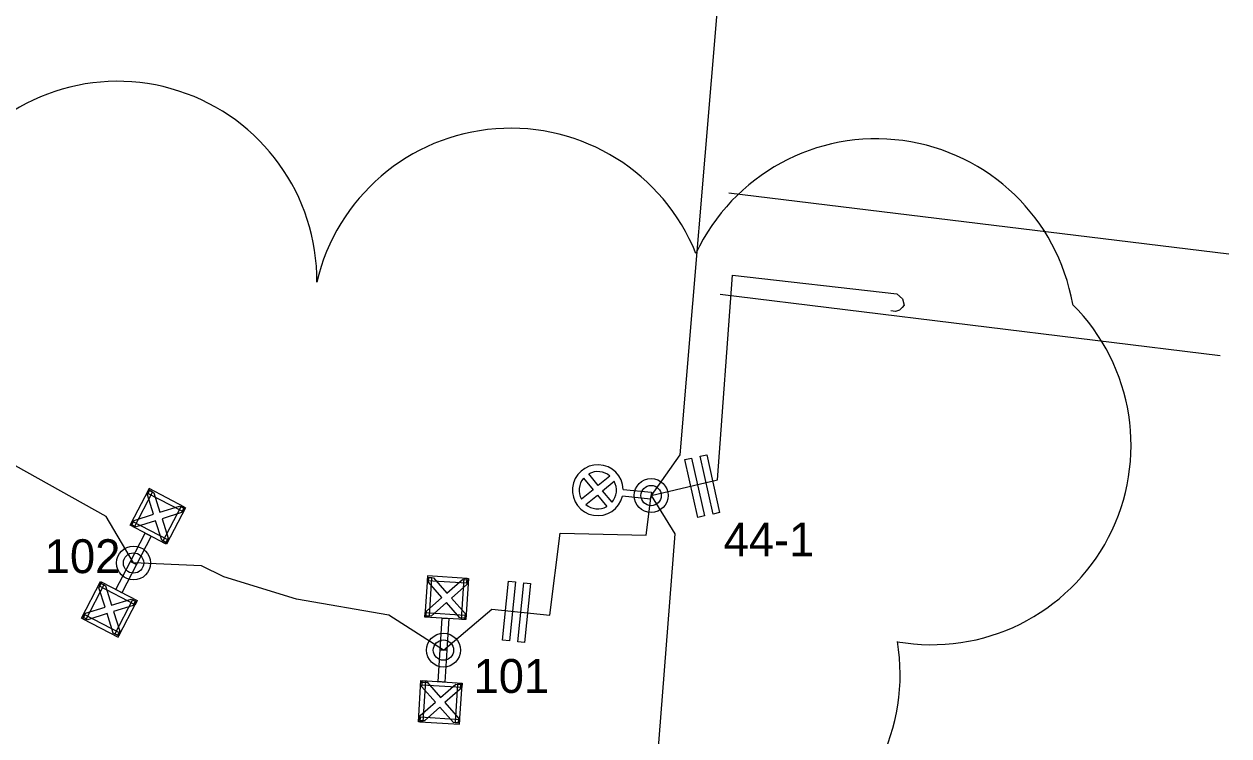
# Model space of a CAD drawing. Extents: x 25497851 to 25498523, y 6686544 to 6687372.
# Drawn here: x 25498190.6 to 25498297.2, y 6686990.4 to 6687053.4 of the extents above; entities that cross this region are included whole.
import ezdxf

# ---------------------------------------------------------------- set-up
doc = ezdxf.new("R2010")
doc.units = 0
for name, color, linetype in [('KAAPELI', 7, 'Continuous'), ('KEYGWT_ANNOTATION', 7, 'Continuous'), ('MUU_SUUNNITELMAVIIVA', 7, 'Continuous'), ('MUU_UV-SUUNNITELMASYMBOLI', 7, 'Continuous'), ('PYLVAS', 7, 'Continuous'), ('TEKSTI_SUUNNITELMA-ALUE', 7, 'Continuous'), ('TieAlue_ajorata', 7, 'Continuous'), ('VALAISIN', 7, 'Continuous')]:
    doc.layers.add(name, color=color, linetype=linetype)

msp = doc.modelspace()

# ---------------------------------------------------------------- linework, layer by layer
at = {"layer": 'KAAPELI'}
for points in [[(25498250.22, 6687059.49), (25498251.96, 6687055.15), (25498248.64, 6687015.33), (25498246.09, 6687011.72)], [(25498246.09, 6687011.72), (25498251.96, 6687013.1), (25498253.29, 6687031.23), (25498267.85, 6687029.58), (25498268.35, 6687029.13), (25498268.49, 6687028.57), (25498268.31, 6687028.35), (25498268.09, 6687028.13), (25498267.72, 6687028.01), (25498267.31, 6687028.08)], [(25498200.27, 6687005.75), (25498197.85, 6687009.86), (25498181.51, 6687018.98), (25498176.94, 6687018.9)], [(25498227.71, 6686998.04), (25498232, 6687001.66), (25498237.11, 6687001.14), (25498238.03, 6687008.39), (25498245.66, 6687008.21), (25498246.09, 6687011.72)], [(25498246.09, 6687011.72), (25498248.18, 6687008.34), (25498245.03, 6686967.87), (25498241.98, 6686963.86)], [(25498227.71, 6686998.04), (25498222.86, 6687001.14), (25498214.69, 6687002.55), (25498208.26, 6687004.51), (25498206.28, 6687005.51), (25498200.27, 6687005.75)]]:
    msp.add_lwpolyline(points, dxfattribs=at)
at = {"layer": 'MUU_SUUNNITELMAVIIVA'}
for centre, radius, start, end in [((25498198.85, 6687030.73), 17.65, 359.5582, 144.5582), ((25498233.67, 6687026.58), 17.65, 21.8381, 166.8381), ((25498266.02, 6687025.64), 17.65, 9.8286, 154.8286), ((25498270.94, 6687016.16), 17.64, 260.0364, 45.0364), ((25498250.49, 6686995.87), 17.65, 224.5286, 9.5286)]:
    msp.add_arc(centre, radius, start, end, dxfattribs=at)
at = {"layer": 'MUU_UV-SUUNNITELMASYMBOLI'}
for p, q in [((25498250.42, 6687015.2), (25498251.01, 6687015.33)), ((25498251.57, 6687010.07), (25498250.42, 6687015.2)), ((25498251.01, 6687015.33), (25498252.15, 6687010.21)), ((25498249.09, 6687014.9), (25498249.68, 6687015.03)), ((25498250.24, 6687009.78), (25498249.09, 6687014.9)), ((25498249.68, 6687015.03), (25498250.82, 6687009.91)), ((25498250.82, 6687009.91), (25498250.24, 6687009.78)), ((25498252.15, 6687010.21), (25498251.57, 6687010.07)), ((25498232.94, 6686998.91), (25498233.47, 6687004.13)), ((25498233.47, 6687004.13), (25498234.07, 6687004.07)), ((25498234.07, 6687004.07), (25498233.54, 6686998.85)), ((25498234.3, 6686998.77), (25498234.82, 6687003.99)), ((25498234.82, 6687003.99), (25498235.42, 6687003.93)), ((25498235.42, 6687003.93), (25498234.89, 6686998.71)), ((25498233.54, 6686998.85), (25498232.94, 6686998.91)), ((25498234.89, 6686998.71), (25498234.3, 6686998.77))]:
    msp.add_line(p, q, dxfattribs=at)
at = {"layer": 'PYLVAS'}
for centre, radius in [((25498246.09, 6687011.72), 1.5), ((25498246.09, 6687011.72), 0.9), ((25498200.27, 6687005.75), 1.5), ((25498200.27, 6687005.75), 1.5), ((25498200.27, 6687005.75), 0.9), ((25498200.27, 6687005.75), 0.9), ((25498227.71, 6686998.04), 1.5), ((25498227.71, 6686998.04), 0.9)]:
    msp.add_circle(centre, radius, dxfattribs=at)
at = {"layer": 'TieAlue_ajorata'}
for p, q in [((25498252.97, 6687038.5), (25498297.24, 6687033.1)), ((25498252.2, 6687029.53), (25498296.47, 6687024.12))]:
    msp.add_line(p, q, dxfattribs=at)
at = {"layer": 'VALAISIN'}
for p, q in [((25498240.11, 6687013.25), (25498240.95, 6687012.23)), ((25498241.41, 6687012.61), (25498240.57, 6687013.63)), ((25498242.44, 6687013.44), (25498241.41, 6687012.61)), ((25498241.79, 6687012.14), (25498242.81, 6687012.98)), ((25498240.95, 6687012.23), (25498239.92, 6687011.39)), ((25498242.63, 6687011.12), (25498241.79, 6687012.14)), ((25498243.62, 6687012.26), (25498246.11, 6687012.01)), ((25498246.11, 6687012.01), (25498246.05, 6687011.41)), ((25498240.3, 6687010.93), (25498241.33, 6687011.76)), ((25498241.33, 6687011.76), (25498242.16, 6687010.74)), ((25498246.05, 6687011.41), (25498243.56, 6687011.66))]:
    msp.add_line(p, q, dxfattribs=at)
for points in [[(25498201.58, 6687012.22), (25498200.01, 6687009.2), (25498200.37, 6687009.02), (25498201.94, 6687012.03)], [(25498202.77, 6687007.77), (25498202.22, 6687009.49), (25498200.5, 6687008.95), (25498200.12, 6687009.14), (25498200.32, 6687009.52), (25498202.04, 6687010.06), (25498201.5, 6687011.78), (25498201.69, 6687012.16), (25498202.07, 6687011.96), (25498202.61, 6687010.24), (25498204.34, 6687010.78), (25498204.71, 6687010.59), (25498204.52, 6687010.21), (25498202.79, 6687009.67), (25498203.34, 6687007.95), (25498203.14, 6687007.57)], [(25498204.59, 6687010.34), (25498204.77, 6687010.69), (25498201.64, 6687012.33), (25498201.46, 6687011.97)], [(25498202.84, 6687007.59), (25498204.52, 6687010.82), (25498204.88, 6687010.64), (25498203.19, 6687007.41)], [(25498199.96, 6687009.09), (25498200.14, 6687009.45), (25498203.27, 6687007.82), (25498203.09, 6687007.46)], [(25498200.01, 6687005.89), (25498201.31, 6687008.39), (25498201.84, 6687008.11), (25498200.54, 6687005.61)], [(25498200.54, 6687005.61), (25498199.24, 6687003.12), (25498198.71, 6687003.4), (25498200.01, 6687005.89)], [(25498226.28, 6687004.48), (25498226.07, 6687001.08), (25498226.47, 6687001.06), (25498226.68, 6687004.45)], [(25498229.17, 6687000.89), (25498227.97, 6687002.25), (25498226.61, 6687001.05), (25498226.19, 6687001.08), (25498226.22, 6687001.5), (25498227.57, 6687002.7), (25498226.37, 6687004.05), (25498226.4, 6687004.47), (25498226.82, 6687004.45), (25498228.02, 6687003.09), (25498229.38, 6687004.29), (25498229.8, 6687004.26), (25498229.77, 6687003.84), (25498228.42, 6687002.64), (25498229.62, 6687001.29), (25498229.59, 6687000.87)], [(25498229.78, 6687003.99), (25498229.81, 6687004.38), (25498226.28, 6687004.6), (25498226.26, 6687004.2)], [(25498197.71, 6687003.92), (25498196.02, 6687000.68), (25498195.67, 6687000.87), (25498197.35, 6687004.1)], [(25498197.78, 6687003.74), (25498198.32, 6687002.02), (25498200.05, 6687002.56), (25498200.42, 6687002.36), (25498200.23, 6687001.99), (25498198.5, 6687001.45), (25498199.05, 6686999.72), (25498198.85, 6686999.35), (25498198.47, 6686999.54), (25498197.93, 6687001.27), (25498196.21, 6687000.72), (25498195.83, 6687000.92), (25498196.03, 6687001.3), (25498197.75, 6687001.84), (25498197.21, 6687003.56), (25498197.4, 6687003.94)], [(25498200.59, 6687002.42), (25498200.4, 6687002.06), (25498197.27, 6687003.69), (25498197.46, 6687004.05)], [(25498229.3, 6687000.76), (25498229.53, 6687004.4), (25498229.93, 6687004.38), (25498229.7, 6687000.74)], [(25498198.96, 6686999.29), (25498200.53, 6687002.31), (25498200.18, 6687002.49), (25498198.6, 6686999.48)], [(25498226.06, 6687000.96), (25498226.09, 6687001.36), (25498229.61, 6687001.14), (25498229.58, 6687000.75)], [(25498195.96, 6687001.17), (25498195.77, 6687000.81), (25498198.9, 6686999.18), (25498199.09, 6686999.54)], [(25498227.41, 6686998.06), (25498227.58, 6687000.87), (25498228.18, 6687000.83), (25498228.01, 6686998.02)], [(25498228.01, 6686998.02), (25498227.83, 6686995.21), (25498227.24, 6686995.25), (25498227.41, 6686998.06)], [(25498226.11, 6686995.32), (25498225.89, 6686991.68), (25498225.49, 6686991.7), (25498225.71, 6686995.34)], [(25498226.25, 6686995.19), (25498227.45, 6686993.84), (25498228.8, 6686995.03), (25498229.22, 6686995), (25498229.2, 6686994.58), (25498227.84, 6686993.39), (25498229.04, 6686992.03), (25498229.02, 6686991.61), (25498228.59, 6686991.64), (25498227.39, 6686992.99), (25498226.04, 6686991.79), (25498225.62, 6686991.82), (25498225.64, 6686992.24), (25498227, 6686993.44), (25498225.8, 6686994.79), (25498225.82, 6686995.21)], [(25498229.35, 6686995.12), (25498229.33, 6686994.72), (25498225.81, 6686994.94), (25498225.83, 6686995.34)], [(25498229.14, 6686991.6), (25498229.35, 6686995), (25498228.95, 6686995.02), (25498228.74, 6686991.63)], [(25498225.63, 6686992.1), (25498225.61, 6686991.7), (25498229.13, 6686991.48), (25498229.15, 6686991.88)]]:
    msp.add_lwpolyline(points, close=True, dxfattribs=at)
for radius, start, end in [(2.25, 1.8898, 174.2275), (1.65, 139.7032, 174.2275), (1.65, 49.7032, 118.7518), (1.65, 354.2275, 28.7518), (2.25, 174.2275, 346.5652), (1.65, 174.2275, 208.7518), (1.65, 319.7032, 354.2275), (1.65, 229.7032, 298.7518)]:
    msp.add_arc((25498241.37, 6687012.19), radius, start, end, dxfattribs=at)

# ---------------------------------------------------------------- texts
at = {"layer": 'KEYGWT_ANNOTATION'}
msp.add_text('44-1', height=3, dxfattribs=at).set_placement((25498252.51, 6687006.33))
at = {"layer": 'TEKSTI_SUUNNITELMA-ALUE'}
for s, p in [('102', (25498192.41, 6687004.85)), ('101', (25498230.37, 6686994.25))]:
    msp.add_text(s, height=3, dxfattribs=at).set_placement(p)

doc.saveas('drawing.dxf')
